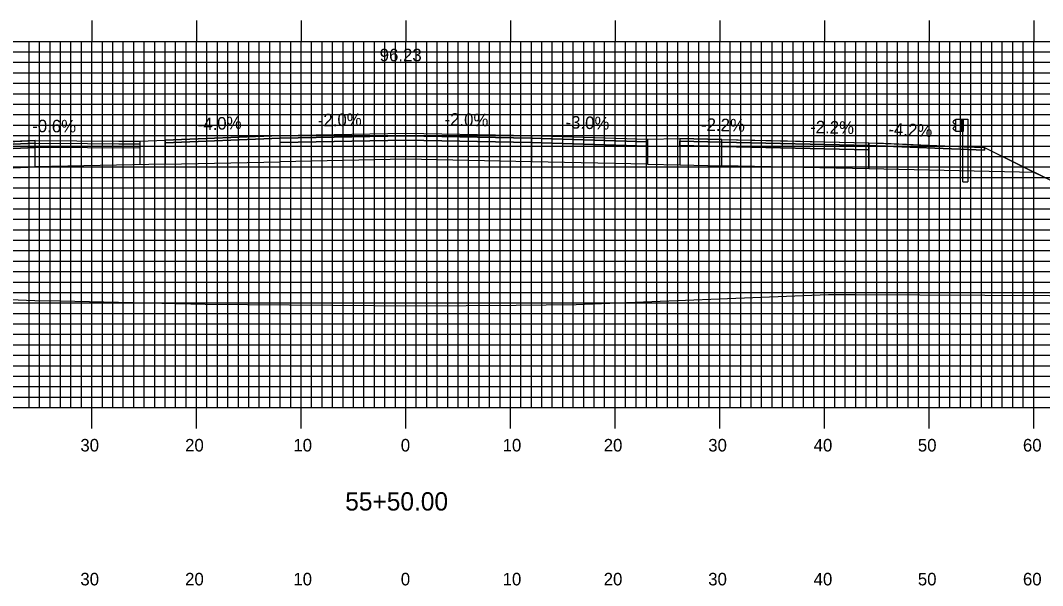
# Model space of a CAD drawing. Extents: x 1756675 to 1757019, y 442591 to 442811.
# Drawn here: x 1756804.3 to 1756901.9, y 442646.6 to 442700.7 of the extents above; entities that cross this region are included whole.
import ezdxf

# ---------------------------------------------------------------- set-up
doc = ezdxf.new("R2010")
doc.units = 0
for name, color, linetype in [('ANNOTATION', 7, 'Continuous'), ('D_Guardrail_Beam_Rt', 7, 'Continuous'), ('D_Roadway_Centerline', 7, 'Continuous'), ('D_Roadway_Centerline_Text', 7, 'Continuous'), ('D_Roadway_Edge_Shoulder', 7, 'Continuous'), ('D_Roadway_Edge_TW', 7, 'Continuous'), ('D_Roadway_Pavement', 7, 'Continuous'), ('D_Roadway_SlopeLines', 7, 'Continuous'), ('D_Roadway_SubGrade', 7, 'Continuous'), ('H_V ANNOTATION', 7, 'Continuous'), ('MAJOR', 7, 'Continuous'), ('MINOR', 7, 'Continuous'), ('S_Roadway_Centerline', 7, 'Continuous')]:
    doc.layers.add(name, color=color, linetype=linetype)

msp = doc.modelspace()

# ---------------------------------------------------------------- linework, layer by layer
at = {"layer": 'ANNOTATION'}
for p, q in [((1756805.652, 442689.186), (1756813.652, 442689.135)), ((1756813.652, 442689.135), (1756815.675, 442689.122)), ((1756813.652, 442688.885), (1756815.675, 442688.872)), ((1756815.675, 442689.122), (1756815.675, 442686.887)), ((1756815.675, 442689.122), (1756815.675, 442689.122)), ((1756818.083, 442686.935), (1756805.652, 442686.686))]:
    msp.add_line(p, q, dxfattribs=at)
at = {"layer": 'D_Guardrail_Beam_Rt'}
for p, q in [((1756893.55, 442691.125), (1756893.407, 442691.025)), ((1756893.407, 442690.882), (1756893.602, 442690.746)), ((1756893.64, 442691.146), (1756893.566, 442691.132)), ((1756893.636, 442690.681), (1756893.636, 442690.611)), ((1756893.64, 442691.229), (1756894.328, 442691.229)), ((1756893.64, 442690.063), (1756893.64, 442691.229)), ((1756894.161, 442691.229), (1756894.161, 442690.063)), ((1756894.265, 442691.229), (1756894.265, 442690.063)), ((1756894.328, 442691.229), (1756894.799, 442691.229)), ((1756894.328, 442691.229), (1756894.328, 442690.063)), ((1756894.799, 442691.229), (1756894.799, 442685.229)), ((1756893.602, 442690.547), (1756893.407, 442690.41)), ((1756893.407, 442690.267), (1756893.55, 442690.167)), ((1756893.566, 442690.161), (1756893.64, 442690.146)), ((1756894.328, 442690.063), (1756893.64, 442690.063)), ((1756894.307, 442685.229), (1756894.307, 442690.063)), ((1756894.307, 442685.229), (1756894.799, 442685.229))]:
    msp.add_line(p, q, dxfattribs=at)
for centre, major_axis, start_param, end_param in [((1756893.457, 442690.953), (-0.0877, 0), 5.323254, 7.243116), ((1756893.574, 442691.091), (-0.0417, 0), 4.907132, 5.323254), ((1756893.557, 442690.681), (0.0789, 0), 0, 0.959931), ((1756893.557, 442690.611), (0.0789, 0), 5.323254, 6.283185), ((1756893.457, 442690.339), (-0.0877, 0), 5.323254, 7.243116), ((1756893.574, 442690.201), (-0.0417, 0), 0.959931, 1.376053)]:
    msp.add_ellipse(centre, major_axis=major_axis, ratio=0.995501, start_param=start_param, end_param=end_param, dxfattribs=at)
at = {"layer": 'D_Roadway_Centerline'}
for p, q in [((1756815.675, 442689.122), (1756818.083, 442689.215)), ((1756864.18, 442689.322), (1756867.27, 442689.371))]:
    msp.add_line(p, q, dxfattribs=at)
for points in [[(1756818.083, 442689.215), (1756829.083, 442689.655), (1756841.083, 442689.895), (1756853.083, 442689.655), (1756864.18, 442689.322)], [(1756752.397, 442674.88), (1756759.582, 442678.221), (1756760.76, 442678.759), (1756780.557, 442688.03), (1756782.617, 442688.126), (1756783.249, 442688.156), (1756783.568, 442688.171), (1756786.437, 442688.304), (1756788.561, 442688.402), (1756791.599, 442688.543), (1756794.135, 442688.66), (1756798.086, 442688.842), (1756801.473, 442688.996), (1756802.431, 442689.04), (1756805.652, 442689.186), (1756809.652, 442689.16), (1756815.675, 442689.122)], [(1756867.27, 442689.371), (1756871.285, 442689.284), (1756876.002, 442689.182), (1756877.547, 442689.149), (1756878.788, 442689.122), (1756881.061, 442689.073), (1756885.339, 442688.98), (1756886.254, 442688.942), (1756886.272, 442688.941), (1756886.274, 442688.941), (1756886.732, 442688.922), (1756888.914, 442688.831), (1756889.572, 442688.804), (1756890.305, 442688.773), (1756893.369, 442688.646), (1756894.454, 442688.601), (1756896.381, 442688.521), (1756897.974, 442687.725), (1756901.149, 442686.138), (1756901.826, 442685.799), (1756902.209, 442685.608)]]:
    msp.add_lwpolyline(points, dxfattribs=at)
at = {"layer": 'D_Roadway_Edge_Shoulder'}
for points in [[(1756829.083, 442689.655), (1756818.083, 442689.215), (1756818.083, 442688.965), (1756829.083, 442689.405)], [(1756853.083, 442689.655), (1756864.18, 442689.322), (1756864.18, 442689.072), (1756853.083, 442689.405)], [(1756871.285, 442689.284), (1756867.27, 442689.371), (1756867.27, 442689.121), (1756871.285, 442689.034)], [(1756885.339, 442688.98), (1756893.369, 442688.646), (1756893.369, 442688.646), (1756896.381, 442688.521), (1756896.381, 442688.271), (1756885.339, 442688.73)]]:
    msp.add_lwpolyline(points, close=True, dxfattribs=at)
at = {"layer": 'D_Roadway_Edge_TW'}
for points in [[(1756829.083, 442689.405), (1756829.083, 442689.655), (1756841.083, 442689.895), (1756853.083, 442689.655), (1756853.083, 442689.405), (1756841.083, 442689.645)], [(1756805.652, 442689.186), (1756791.599, 442688.543), (1756791.599, 442688.293), (1756805.652, 442688.936)], [(1756871.285, 442689.284), (1756885.339, 442688.98), (1756885.339, 442688.73), (1756871.285, 442689.034)]]:
    msp.add_lwpolyline(points, close=True, dxfattribs=at)
at = {"layer": 'D_Roadway_Pavement'}
for points in [[(1756829.083, 442688.988), (1756829.083, 442689.405), (1756841.083, 442689.645), (1756853.083, 442689.405), (1756853.083, 442688.988), (1756841.083, 442689.228)], [(1756805.652, 442688.936), (1756791.599, 442688.293), (1756791.599, 442687.876), (1756805.652, 442688.52)], [(1756805.652, 442688.936), (1756815.675, 442688.872), (1756815.675, 442688.455), (1756805.652, 442688.52)], [(1756853.083, 442689.405), (1756864.18, 442689.072), (1756864.18, 442688.655), (1756853.083, 442688.988)], [(1756871.285, 442689.034), (1756867.27, 442689.121), (1756867.27, 442688.704), (1756871.285, 442688.617)], [(1756871.285, 442689.034), (1756885.339, 442688.73), (1756885.339, 442688.313), (1756871.285, 442688.617)]]:
    msp.add_lwpolyline(points, close=True, dxfattribs=at)
msp.add_lwpolyline([(1756885.339, 442688.73), (1756885.339, 442688.313)], dxfattribs=at)
msp.add_lwpolyline([(1756885.339, 442688.73), (1756885.339, 442688.313)], dxfattribs=at)
at = {"layer": 'D_Roadway_SlopeLines'}
msp.add_lwpolyline([(1756896.381, 442688.521), (1756924.89, 442674.392)], dxfattribs=at)
at = {"layer": 'D_Roadway_SubGrade'}
msp.add_line((1756864.18, 442686.933), (1756867.27, 442686.866), dxfattribs=at)
for points in [[(1756829.083, 442689.405), (1756818.083, 442688.965), (1756818.083, 442686.935), (1756829.083, 442687.155)], [(1756829.083, 442687.155), (1756829.083, 442688.988), (1756841.083, 442689.228), (1756853.083, 442688.988), (1756853.083, 442687.155), (1756841.083, 442687.395)], [(1756853.083, 442688.988), (1756864.18, 442688.655), (1756864.18, 442689.072), (1756864.18, 442686.933), (1756853.083, 442687.155)], [(1756871.285, 442688.617), (1756867.27, 442688.704), (1756867.27, 442689.121), (1756867.27, 442686.866), (1756871.285, 442686.784)], [(1756871.285, 442688.617), (1756885.339, 442688.313), (1756885.339, 442686.48), (1756871.285, 442686.784)], [(1756885.339, 442688.313), (1756885.339, 442688.73), (1756896.381, 442688.271), (1756896.381, 442688.521), (1756901.149, 442686.138), (1756885.339, 442686.48)], [(1756805.652, 442688.52), (1756791.599, 442687.876), (1756791.599, 442686.043), (1756805.652, 442686.686)]]:
    msp.add_lwpolyline(points, close=True, dxfattribs=at)
at = {"layer": 'MAJOR'}
for p, q in [((1756811.083, 442700.669), (1756811.083, 442698.665)), ((1756821.083, 442700.669), (1756821.083, 442698.665)), ((1756831.083, 442700.669), (1756831.083, 442698.665)), ((1756841.083, 442700.669), (1756841.083, 442698.665)), ((1756851.083, 442700.669), (1756851.083, 442698.665)), ((1756861.083, 442700.669), (1756861.083, 442698.665)), ((1756871.083, 442700.669), (1756871.083, 442698.665)), ((1756881.083, 442700.669), (1756881.083, 442698.665)), ((1756891.083, 442700.669), (1756891.083, 442698.665)), ((1756901.083, 442700.669), (1756901.083, 442698.665)), ((1756701.083, 442698.665), (1756981.083, 442698.665)), ((1756701.083, 442698.665), (1756981.083, 442698.665)), ((1756811.083, 442663.665), (1756811.083, 442698.665)), ((1756821.083, 442663.665), (1756821.083, 442698.665)), ((1756831.083, 442663.665), (1756831.083, 442698.665)), ((1756841.083, 442663.665), (1756841.083, 442698.665)), ((1756851.083, 442663.665), (1756851.083, 442698.665)), ((1756861.083, 442663.665), (1756861.083, 442698.665)), ((1756871.083, 442663.665), (1756871.083, 442698.665)), ((1756881.083, 442663.665), (1756881.083, 442698.665)), ((1756891.083, 442663.665), (1756891.083, 442698.665)), ((1756901.083, 442663.665), (1756901.083, 442698.665)), ((1756701.083, 442693.665), (1756981.083, 442693.665)), ((1756701.083, 442688.665), (1756981.083, 442688.665)), ((1756701.083, 442683.665), (1756981.083, 442683.665)), ((1756701.083, 442678.665), (1756981.083, 442678.665)), ((1756701.083, 442673.665), (1756981.083, 442673.665)), ((1756701.083, 442668.665), (1756981.083, 442668.665)), ((1756701.083, 442663.665), (1756981.083, 442663.665)), ((1756701.083, 442663.665), (1756981.083, 442663.665)), ((1756811.083, 442661.661), (1756811.083, 442663.665)), ((1756821.083, 442661.661), (1756821.083, 442663.665)), ((1756831.083, 442661.661), (1756831.083, 442663.665)), ((1756841.083, 442661.661), (1756841.083, 442663.665)), ((1756851.083, 442661.661), (1756851.083, 442663.665)), ((1756861.083, 442661.661), (1756861.083, 442663.665)), ((1756871.083, 442661.661), (1756871.083, 442663.665)), ((1756881.083, 442661.661), (1756881.083, 442663.665)), ((1756891.083, 442661.661), (1756891.083, 442663.665)), ((1756901.083, 442661.661), (1756901.083, 442663.665))]:
    msp.add_line(p, q, dxfattribs=at)
at = {"layer": 'MINOR'}
for p, q in [((1756805.083, 442663.665), (1756805.083, 442698.665)), ((1756806.083, 442663.665), (1756806.083, 442698.665)), ((1756807.083, 442663.665), (1756807.083, 442698.665)), ((1756808.083, 442663.665), (1756808.083, 442698.665)), ((1756809.083, 442663.665), (1756809.083, 442698.665)), ((1756810.083, 442663.665), (1756810.083, 442698.665)), ((1756812.083, 442663.665), (1756812.083, 442698.665)), ((1756813.083, 442663.665), (1756813.083, 442698.665)), ((1756814.083, 442663.665), (1756814.083, 442698.665)), ((1756815.083, 442663.665), (1756815.083, 442698.665)), ((1756816.083, 442663.665), (1756816.083, 442698.665)), ((1756817.083, 442663.665), (1756817.083, 442698.665)), ((1756818.083, 442663.665), (1756818.083, 442698.665)), ((1756819.083, 442663.665), (1756819.083, 442698.665)), ((1756820.083, 442663.665), (1756820.083, 442698.665)), ((1756822.083, 442663.665), (1756822.083, 442698.665)), ((1756823.083, 442663.665), (1756823.083, 442698.665)), ((1756824.083, 442663.665), (1756824.083, 442698.665)), ((1756825.083, 442663.665), (1756825.083, 442698.665)), ((1756826.083, 442663.665), (1756826.083, 442698.665)), ((1756827.083, 442663.665), (1756827.083, 442698.665)), ((1756828.083, 442663.665), (1756828.083, 442698.665)), ((1756829.083, 442663.665), (1756829.083, 442698.665)), ((1756830.083, 442663.665), (1756830.083, 442698.665)), ((1756832.083, 442663.665), (1756832.083, 442698.665)), ((1756833.083, 442663.665), (1756833.083, 442698.665)), ((1756834.083, 442663.665), (1756834.083, 442698.665)), ((1756835.083, 442663.665), (1756835.083, 442698.665)), ((1756836.083, 442663.665), (1756836.083, 442698.665)), ((1756837.083, 442663.665), (1756837.083, 442698.665)), ((1756838.083, 442663.665), (1756838.083, 442698.665)), ((1756839.083, 442663.665), (1756839.083, 442698.665)), ((1756840.083, 442663.665), (1756840.083, 442698.665)), ((1756842.083, 442663.665), (1756842.083, 442698.665)), ((1756843.083, 442663.665), (1756843.083, 442698.665)), ((1756844.083, 442663.665), (1756844.083, 442698.665)), ((1756845.083, 442663.665), (1756845.083, 442698.665)), ((1756846.083, 442663.665), (1756846.083, 442698.665)), ((1756847.083, 442663.665), (1756847.083, 442698.665)), ((1756848.083, 442663.665), (1756848.083, 442698.665)), ((1756849.083, 442663.665), (1756849.083, 442698.665)), ((1756850.083, 442663.665), (1756850.083, 442698.665)), ((1756852.083, 442663.665), (1756852.083, 442698.665)), ((1756853.083, 442663.665), (1756853.083, 442698.665)), ((1756854.083, 442663.665), (1756854.083, 442698.665)), ((1756855.083, 442663.665), (1756855.083, 442698.665)), ((1756856.083, 442663.665), (1756856.083, 442698.665)), ((1756857.083, 442663.665), (1756857.083, 442698.665)), ((1756858.083, 442663.665), (1756858.083, 442698.665)), ((1756859.083, 442663.665), (1756859.083, 442698.665)), ((1756860.083, 442663.665), (1756860.083, 442698.665)), ((1756862.083, 442663.665), (1756862.083, 442698.665)), ((1756863.083, 442663.665), (1756863.083, 442698.665)), ((1756864.083, 442663.665), (1756864.083, 442698.665)), ((1756865.083, 442663.665), (1756865.083, 442698.665)), ((1756866.083, 442663.665), (1756866.083, 442698.665)), ((1756867.083, 442663.665), (1756867.083, 442698.665)), ((1756868.083, 442663.665), (1756868.083, 442698.665)), ((1756869.083, 442663.665), (1756869.083, 442698.665)), ((1756870.083, 442663.665), (1756870.083, 442698.665)), ((1756872.083, 442663.665), (1756872.083, 442698.665)), ((1756873.083, 442663.665), (1756873.083, 442698.665)), ((1756874.083, 442663.665), (1756874.083, 442698.665)), ((1756875.083, 442663.665), (1756875.083, 442698.665)), ((1756876.083, 442663.665), (1756876.083, 442698.665)), ((1756877.083, 442663.665), (1756877.083, 442698.665)), ((1756878.083, 442663.665), (1756878.083, 442698.665)), ((1756879.083, 442663.665), (1756879.083, 442698.665)), ((1756880.083, 442663.665), (1756880.083, 442698.665)), ((1756882.083, 442663.665), (1756882.083, 442698.665)), ((1756883.083, 442663.665), (1756883.083, 442698.665)), ((1756884.083, 442663.665), (1756884.083, 442698.665)), ((1756885.083, 442663.665), (1756885.083, 442698.665)), ((1756886.083, 442663.665), (1756886.083, 442698.665)), ((1756887.083, 442663.665), (1756887.083, 442698.665)), ((1756888.083, 442663.665), (1756888.083, 442698.665)), ((1756889.083, 442663.665), (1756889.083, 442698.665)), ((1756890.083, 442663.665), (1756890.083, 442698.665)), ((1756892.083, 442663.665), (1756892.083, 442698.665)), ((1756893.083, 442663.665), (1756893.083, 442698.665)), ((1756894.083, 442663.665), (1756894.083, 442698.665)), ((1756895.083, 442663.665), (1756895.083, 442698.665)), ((1756896.083, 442663.665), (1756896.083, 442698.665)), ((1756897.083, 442663.665), (1756897.083, 442698.665)), ((1756898.083, 442663.665), (1756898.083, 442698.665)), ((1756899.083, 442663.665), (1756899.083, 442698.665)), ((1756900.083, 442663.665), (1756900.083, 442698.665)), ((1756701.083, 442697.665), (1756981.083, 442697.665)), ((1756701.083, 442696.665), (1756981.083, 442696.665)), ((1756701.083, 442695.665), (1756981.083, 442695.665)), ((1756701.083, 442694.665), (1756981.083, 442694.665)), ((1756701.083, 442692.665), (1756981.083, 442692.665)), ((1756701.083, 442691.665), (1756981.083, 442691.665)), ((1756701.083, 442690.665), (1756981.083, 442690.665)), ((1756701.083, 442689.665), (1756981.083, 442689.665)), ((1756701.083, 442687.665), (1756981.083, 442687.665)), ((1756701.083, 442686.665), (1756981.083, 442686.665)), ((1756701.083, 442685.665), (1756981.083, 442685.665)), ((1756701.083, 442684.665), (1756981.083, 442684.665)), ((1756701.083, 442682.665), (1756981.083, 442682.665)), ((1756701.083, 442681.665), (1756981.083, 442681.665)), ((1756701.083, 442680.665), (1756981.083, 442680.665)), ((1756701.083, 442679.665), (1756981.083, 442679.665)), ((1756701.083, 442677.665), (1756981.083, 442677.665)), ((1756701.083, 442676.665), (1756981.083, 442676.665)), ((1756701.083, 442675.665), (1756981.083, 442675.665)), ((1756701.083, 442674.665), (1756981.083, 442674.665)), ((1756701.083, 442672.665), (1756981.083, 442672.665)), ((1756701.083, 442671.665), (1756981.083, 442671.665)), ((1756701.083, 442670.665), (1756981.083, 442670.665)), ((1756701.083, 442669.665), (1756981.083, 442669.665)), ((1756701.083, 442667.665), (1756981.083, 442667.665)), ((1756701.083, 442666.665), (1756981.083, 442666.665)), ((1756701.083, 442665.665), (1756981.083, 442665.665)), ((1756701.083, 442664.665), (1756981.083, 442664.665))]:
    msp.add_line(p, q, dxfattribs=at)
at = {"layer": 'S_Roadway_Centerline'}
msp.add_lwpolyline([(1756701.083, 442674.806), (1756701.677, 442674.807), (1756706.125, 442674.789), (1756709.099, 442674.81), (1756750.005, 442674.906), (1756753.923, 442674.864), (1756780.551, 442674.653), (1756793.339, 442674.456), (1756796.089, 442674.271), (1756805.615, 442673.9), (1756808.091, 442673.878), (1756821.911, 442673.544), (1756842.059, 442673.399), (1756851.642, 442673.436), (1756857.377, 442673.524), (1756881.459, 442674.478), (1756884.01, 442674.461), (1756914.988, 442674.299), (1756935.298, 442674.49), (1756942.874, 442674.673), (1756956.22, 442674.702), (1756981.083, 442675.143)], dxfattribs=at)

# ---------------------------------------------------------------- texts
at = {"layer": 'ANNOTATION'}
for s, rotation, p in [('-2.0%', 1.14576, (1756832.689, 442690.527)), ('-2.0%', 358.85424, (1756844.769, 442690.622)), ('-3.0%', 358.28164, (1756856.328, 442690.358)), ('-0.6%', 359.62996, (1756805.375, 442689.988)), ('-4.0%', 2.29061, (1756821.215, 442690.142)), ('-2.2%', 358.75943, (1756869.283, 442690.128)), ('-2.2%', 358.75981, (1756879.71, 442689.902)), ('-4.2%', 357.61961, (1756887.183, 442689.691))]:
    msp.add_text(s, height=1.2, rotation=rotation, dxfattribs=at).set_placement(p)
at = {"layer": 'D_Roadway_Centerline'}
for s, p in [('C', (1756841.078, 442689.895)), ('L', (1756841.083, 442689.888))]:
    msp.add_text(s, height=0.0146, dxfattribs=at).set_placement(p)
at = {"layer": 'D_Roadway_Centerline_Text'}
msp.add_text('96.23', height=1.2, dxfattribs=at).set_placement((1756838.584, 442696.763))
at = {"layer": 'H_V ANNOTATION'}
for s, height, p in [('30', 1.2, (1756809.98, 442659.465)), ('20', 1.2, (1756819.991, 442659.465)), ('10', 1.2, (1756830.334, 442659.465)), ('0', 1.2, (1756840.601, 442659.465)), ('10', 1.2, (1756850.334, 442659.465)), ('20', 1.2, (1756859.991, 442659.465)), ('30', 1.2, (1756869.98, 442659.465)), ('40', 1.2, (1756880.055, 442659.465)), ('50', 1.2, (1756890.012, 442659.465)), ('60', 1.2, (1756900.055, 442659.465)), ('55+50.00', 1.75, (1756835.293, 442653.821)), ('30', 1.2, (1756809.98, 442646.665)), ('20', 1.2, (1756819.991, 442646.665)), ('10', 1.2, (1756830.334, 442646.665)), ('0', 1.2, (1756840.601, 442646.665)), ('10', 1.2, (1756850.334, 442646.665)), ('20', 1.2, (1756859.991, 442646.665)), ('30', 1.2, (1756869.98, 442646.665)), ('40', 1.2, (1756880.055, 442646.665)), ('50', 1.2, (1756890.012, 442646.665)), ('60', 1.2, (1756900.055, 442646.665))]:
    msp.add_text(s, height=height, dxfattribs=at).set_placement(p)

doc.saveas('drawing.dxf')
